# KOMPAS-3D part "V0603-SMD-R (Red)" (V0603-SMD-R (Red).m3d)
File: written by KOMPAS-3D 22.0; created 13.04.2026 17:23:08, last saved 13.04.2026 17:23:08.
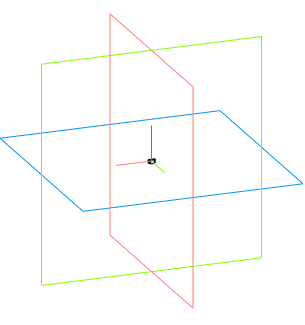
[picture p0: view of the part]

Document properties: Автор: Andrey; Полное имя файла: C:\Users\User1\Documents\V0603-SMD-R (Red).m3d

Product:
- Part/product: V0603-SMD-R (Red)

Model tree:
1. Операция без истории:1
2. Операция без истории:2
3. Операция без истории:3
4. Операция без истории:4
5. Операция без истории:5
6. Операция без истории:6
